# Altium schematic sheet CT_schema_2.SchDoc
size 313 x 185 mm
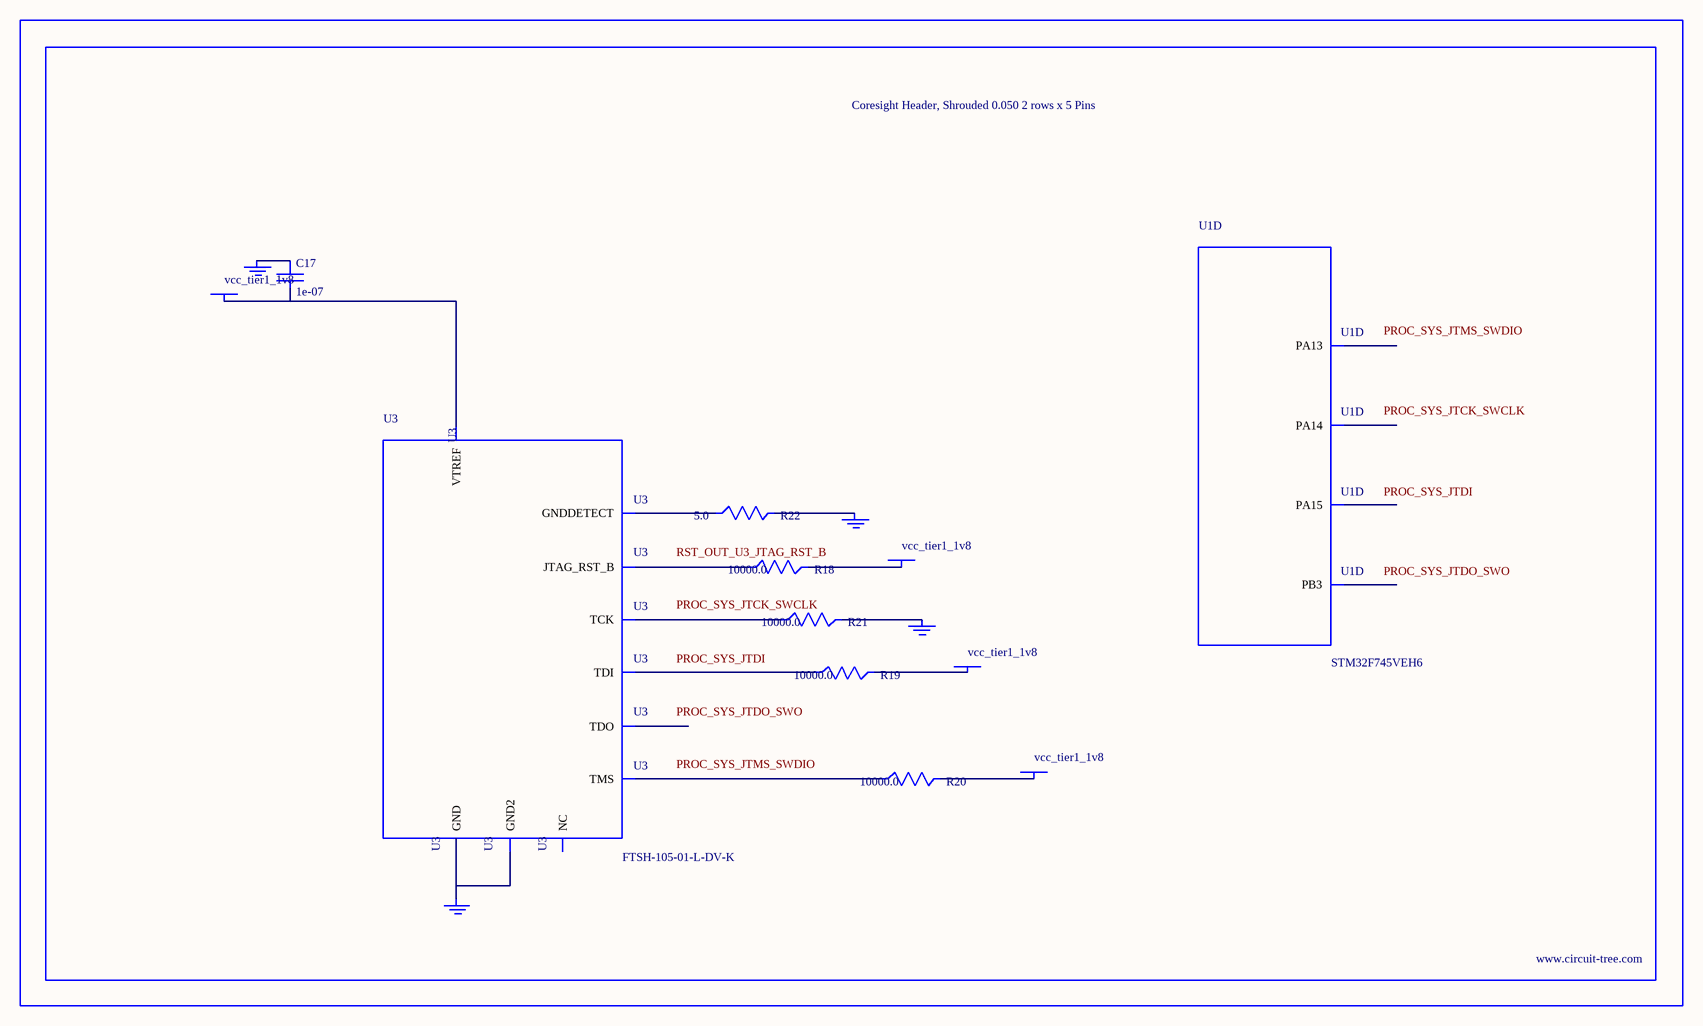
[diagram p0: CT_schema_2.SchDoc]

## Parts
BORDER1  (no value)
C17  1e-07  [C0402]
GND_INSTANCE_1_0  (no value)
GND_INSTANCE_1_1  (no value)
GND_INSTANCE_1_2  (no value)
GND_INSTANCE_1_3  (no value)
POWER_INSTANCE_1_0  vcc_tier1_1v8
POWER_INSTANCE_1_1  vcc_tier1_1v8
POWER_INSTANCE_1_2  vcc_tier1_1v8
POWER_INSTANCE_1_3  vcc_tier1_1v8
R18  10000.0  [R0603]
R19  10000.0  [R0603]
R20  10000.0  [R0603]
R21  10000.0  [R0603]
R22  5.0  [R0603]
U1  STM32F745VEH6  [TFBGA100]  (part D of 10)
U3  FTSH-105-01-L-DV-K  [SAMTEC_FTSH-105-01-L-DV-K]

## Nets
NetC17_1: C17.1 GND_INSTANCE_1_0.0(GND)
NetC17_2: C17.2 POWER_INSTANCE_1_0.0(PWR) U3.1(VTREF)
NetGND_INSTANCE_1_1_0: GND_INSTANCE_1_1.0(GND) R21.2
NetGND_INSTANCE_1_2_0: GND_INSTANCE_1_2.0(GND) R22.2
NetGND_INSTANCE_1_3_0: GND_INSTANCE_1_3.0(GND) U3.3(GND) U3.5(GND2)
NetPOWER_INSTANCE_1_1_0: POWER_INSTANCE_1_1.0(PWR) R20.2
NetPOWER_INSTANCE_1_2_0: POWER_INSTANCE_1_2.0(PWR) R19.2
NetPOWER_INSTANCE_1_3_0: POWER_INSTANCE_1_3.0(PWR) R18.2
NetR18_1: R18.1 U3.10(JTAG_RST_B)
NetR19_1: R19.1 U3.8(TDI)
NetR20_1: R20.1 U3.2(TMS)
NetR21_1: R21.1 U3.4(TCK)
NetR22_1: R22.1 U3.9(GNDDETECT)

Not connected (* = marked no-connect by the designer): U1 A7(PB3) A8(PA15) A9(PA14) A10(PA13); U3 6(TDO) 7(NC)

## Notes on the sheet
- Labels drawn without touching a wire or pin: PROC_SYS_JTCK_SWCLK, PROC_SYS_JTDI, PROC_SYS_JTDO_SWO, PROC_SYS_JTMS_SWDIO, RST_OUT_U3_JTAG_RST_B

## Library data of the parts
BORDER1 = BORDER_PAGE1
C17 = C0402C104K3RACTU
GND_INSTANCE_1_0-GND_INSTANCE_1_3 = GND
POWER_INSTANCE_1_0-POWER_INSTANCE_1_3 = PWR
R18-R21 = RC0603JR-0710KL
R22 = ERJ-3GEYJ5R1V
